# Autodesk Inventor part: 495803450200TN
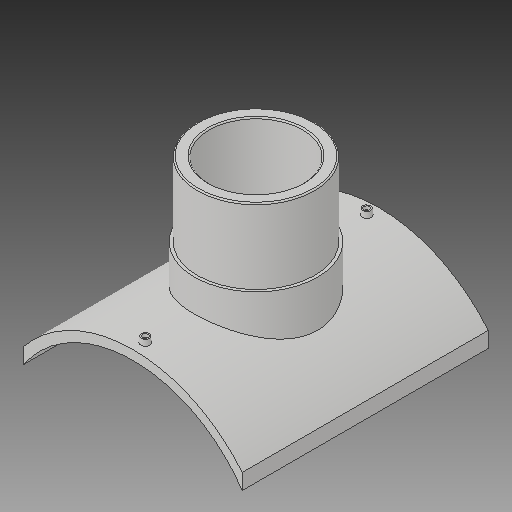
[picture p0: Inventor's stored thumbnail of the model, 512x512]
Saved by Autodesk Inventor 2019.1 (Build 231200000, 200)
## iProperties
Created: 2017-10
Part Number: 495803450200TN
Material: Generic
Description: PLASSON BRANCH SADDLE  400-450x200
Document SubType Name: Modeling
Designer: KIM
Mass: 2754.05 g
Surface Area: 3037.44 cm^2
Volume: 2754.05 cm^3
Density: 1 g/cm^3
Appearance: Default
Author: KIM
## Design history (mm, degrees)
derived "495803.ipt"
feature "Solid1::495803.ipt"
tag "TaggingFeature1"
body "Solid1"
other parameters: "d1" = 16, "d2" = 373, "d4" = 0, "d12" = 250.6, "d13" = 14, "d14" = 189, "d16" = 5 deg, "d18" = 4, "d19" = 14, "d20" = 0, "d21" = 3, "d22" = 0, "d23" = 423, "d25" = 16, "d28" = 0, "d29" = 9.6, "d31" = 0, "d32" = 91, "d33" = 0, "d34" = 4.5, "d37" = 127.4, "d38" = 0, "d39" = 2.25, "B_" = 373, "H_" = 182, "x_" = 16, "D_" = 16
